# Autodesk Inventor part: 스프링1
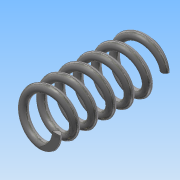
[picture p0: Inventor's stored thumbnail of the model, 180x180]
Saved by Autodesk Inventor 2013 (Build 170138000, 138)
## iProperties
Created: 2015-12
Part Number: 스프링1
Material: 강철, 탄소
Document SubType Name: Modeling
Designer: Administrator
Density: 7.87 g/cm^3
Mass: 16.5127 g
Surface Area: 28.4714 cm^2
Volume: 2.09818 cm^3
Author: Administrator
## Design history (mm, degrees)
sketch "스케치1"
  geometry: L1 (0, 0)-(8, 0); L2 (0, 0)-(0, 42); L3 (0, 42)-(8, 42); C1 r 1.5 at (8, 0)
  constraints: 6 end point, 2 perpendicular, 1 centre point, 1 coincident, 1 horizontal
  dimensions: "d0" = 8 distance of L1.start L1.end; "d1" = 3 diameter of C1; "d2" = 41.99994 distance of L1.start L2.end (derived); "d4" = 8 distance of L2.end L3.end
feature "코일1" sketch "스케치1" pitch "d5" = 10; turns "d7" = 6; dims "d6" = 41.99994 (= d2), "d8" = 0, angle "d9" = 90 deg, angle "d10" = 90 deg, "d11" = 0, "d12" = 0
sketch "스케치2"
  geometry: L1 (42, 16)-(0, 16); L2 (0, 16)-(0, -16); L3 (0, -16)-(42, -16); L4 (42, -16)-(42, 16); 2 further points
  constraints: 8 end point, 2 parallel, 1 coincident, 1 horizontal, 1 midpoint, 1 perpendicular
  dimensions: "d13" = 32 distance between parallel lines of L3 L1; "d15" = 42 distance between parallel lines of L2 L4 (derived)
extrude "돌출1" sketch "스케치2" stored distance "d16" = 10; taper "d17" = 0 deg
node "솔리드1"
